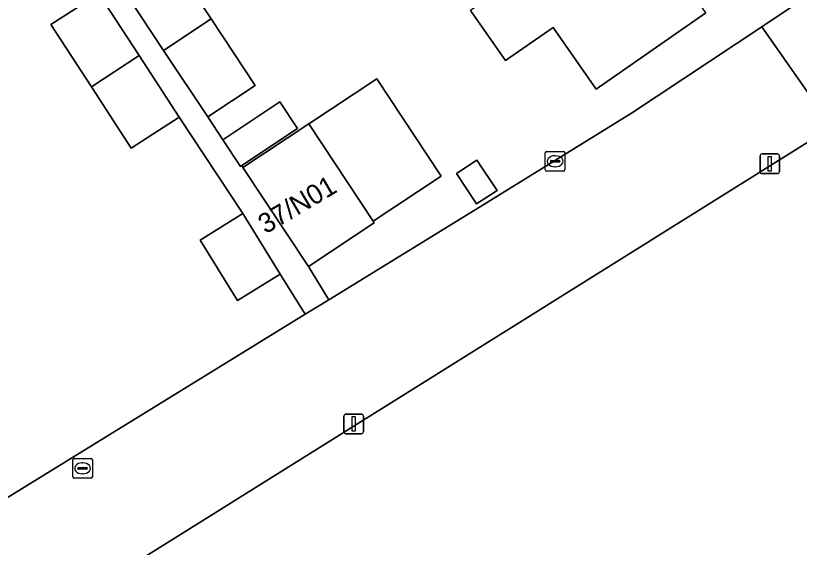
# Model space of a CAD drawing. Extents: x 159352 to 160617, y 385888 to 387323.
# Drawn here: x 159852.67 to 159892.59, y 386193.52 to 386220.6 of the extents above; entities that cross this region are included whole.
import ezdxf

# ---------------------------------------------------------------- set-up
doc = ezdxf.new("R2010")
doc.units = 0
for name, color, linetype in [('IMGEO_Erf', 7, 'Continuous'), ('IMGEO_Kolk', 7, 'Continuous'), ('IMGEO_Lichtmast', 7, 'Continuous'), ('IMGEO_Muur', 7, 'Continuous'), ('IMGEO_Pand', 7, 'Continuous'), ('IMGEO_Pand_nummerreeks', 7, 'Continuous'), ('IMGEO_Rijbaan_lokaal_open', 7, 'Continuous'), ('IMGEO_Voetpad_open', 7, 'Continuous')]:
    doc.layers.add(name, color=color, linetype=linetype)

msp = doc.modelspace()

# ---------------------------------------------------------------- linework, layer by layer
at = {"layer": 'IMGEO_Erf'}
for points in [[(159807.126, 386245.89), (159842.817, 386190.245), (159867.411, 386205.386), (159866.139, 386207.439), (159863.971, 386206.096), (159862.068, 386209.169), (159864.234, 386210.517), (159860.999, 386215.43), (159858.551, 386213.846), (159856.53, 386216.969), (159854.468, 386220.155), (159856.914, 386221.738), (159855.157, 386224.453), (159855.01, 386224.357), (159852.709, 386222.865), (159848.806, 386228.881), (159848.654, 386228.783), (159844.958, 386234.482)], [(159860.733, 386223.291), (159862.622, 386220.437), (159864.871, 386217.041), (159862.451, 386215.439), (159863.218, 386214.28), (159866.131, 386216.208), (159867.031, 386214.85), (159864.185, 386212.965), (159864.248, 386212.87), (159867.604, 386215.088), (159871.07, 386217.378), (159874.34, 386212.429), (159870.874, 386210.139), (159870.938, 386210.043), (159867.581, 386207.825), (159868.623, 386206.132), (159876.292, 386210.853), (159884.045, 386215.626), (159890.682, 386220.04), (159892.54, 386221.275)], [(159887.827, 386220.739), (159882.244, 386216.85), (159880.05, 386220.005), (159877.625, 386218.318), (159875.849, 386220.871)]]:
    msp.add_lwpolyline(points, dxfattribs=at)
msp.add_lwpolyline([(159875.128, 386212.559), (159876.17, 386213.247), (159877.191, 386211.702), (159876.149, 386211.013)], close=True, dxfattribs=at)
at = {"layer": 'IMGEO_Kolk'}
for p, q in [((159879.652, 386212.756), (159879.652, 386213.608)), ((159879.727, 386213.682), (159880.579, 386213.682)), ((159880.14, 386213.462), (159880.165, 386213.462)), ((159880.653, 386213.608), (159880.653, 386212.756)), ((159879.911, 386213.176), (159879.911, 386213.188)), ((159880.349, 386213.139), (159879.951, 386213.139)), ((159879.954, 386213.225), (159880.352, 386213.225)), ((159880.395, 386213.188), (159880.395, 386213.176)), ((159880.579, 386212.682), (159879.727, 386212.682)), ((159880.163, 386212.902), (159880.138, 386212.902)), ((159855.575, 386197.113), (159855.575, 386197.965)), ((159855.65, 386198.039), (159856.502, 386198.039)), ((159856.576, 386197.965), (159856.576, 386197.113)), ((159855.834, 386197.533), (159855.834, 386197.545)), ((159856.272, 386197.496), (159855.874, 386197.496)), ((159855.877, 386197.582), (159856.275, 386197.582)), ((159856.063, 386197.819), (159856.088, 386197.819)), ((159856.318, 386197.545), (159856.318, 386197.533)), ((159856.086, 386197.259), (159856.061, 386197.259)), ((159856.502, 386197.039), (159855.65, 386197.039))]:
    msp.add_line(p, q, dxfattribs=at)
for points in [[(159879.652, 386212.756), (159879.652, 386213.608)], [(159879.727, 386213.682), (159880.579, 386213.682)], [(159880.653, 386213.608), (159880.653, 386212.756)], [(159880.579, 386212.682), (159879.727, 386212.682)], [(159855.575, 386197.113), (159855.575, 386197.965)], [(159855.65, 386198.039), (159856.502, 386198.039)], [(159856.576, 386197.965), (159856.576, 386197.113)], [(159856.502, 386197.039), (159855.65, 386197.039)]]:
    msp.add_lwpolyline(points, dxfattribs=at)
for centre, radius, start, end in [((159879.729, 386213.606), 0.0765, 91.552, 178.448), ((159879.729, 386213.606), 0.0765, 91.552, 178.448), ((159880.577, 386213.606), 0.0765, 1.552, 88.448), ((159880.577, 386213.606), 0.0765, 1.552, 88.448), ((159879.951, 386213.185), 0.0403, 85.8775, 175.7526), ((159879.948, 386213.175), 0.0366, 178.938, 274.7102), ((159880.352, 386213.182), 0.043, 264.8664, 352.4533), ((159880.356, 386213.187), 0.0386, 1.7309, 96.639), ((159879.729, 386212.758), 0.0765, 181.552, 268.448), ((159879.729, 386212.758), 0.0765, 181.552, 268.448), ((159880.577, 386212.758), 0.0765, 271.552, 358.448), ((159880.577, 386212.758), 0.0765, 271.552, 358.448), ((159855.652, 386197.963), 0.0765, 91.552, 178.448), ((159855.652, 386197.963), 0.0765, 91.552, 178.448), ((159856.5, 386197.963), 0.0765, 1.552, 88.448), ((159856.5, 386197.963), 0.0765, 1.552, 88.448), ((159855.874, 386197.542), 0.0403, 85.8775, 175.7526), ((159855.871, 386197.532), 0.0366, 178.938, 274.7102), ((159856.275, 386197.539), 0.043, 264.8664, 352.4533), ((159856.279, 386197.544), 0.0386, 1.7309, 96.639), ((159855.652, 386197.115), 0.0765, 181.552, 268.448), ((159855.652, 386197.115), 0.0765, 181.552, 268.448), ((159856.5, 386197.115), 0.0765, 271.552, 358.448), ((159856.5, 386197.115), 0.0765, 271.552, 358.448)]:
    msp.add_arc(centre, radius, start, end, dxfattribs=at)
for centre, major_axis, ratio, start_param, end_param in [((159880.139, 386213.182), (-0.387, 0.002), 0.722429, 4.712389, 7.853982), ((159880.164, 386213.182), (-0.39, 0.002), 0.717154, 1.570796, 4.712389), ((159856.062, 386197.539), (-0.387, 0.002), 0.722429, 4.712389, 7.853982), ((159856.087, 386197.539), (-0.39, 0.002), 0.717154, 1.570796, 4.712389)]:
    msp.add_ellipse(centre, major_axis=major_axis, ratio=ratio, start_param=start_param, end_param=end_param, dxfattribs=at)
at = {"layer": 'IMGEO_Lichtmast'}
for p, q in [((159890.592, 386212.656), (159890.592, 386213.456)), ((159890.592, 386213.456), (159890.592, 386212.656)), ((159890.692, 386213.556), (159891.482, 386213.556)), ((159891.482, 386213.556), (159890.692, 386213.556)), ((159891.582, 386213.456), (159891.582, 386212.656)), ((159891.582, 386212.656), (159891.582, 386213.456)), ((159891.482, 386212.556), (159890.692, 386212.556)), ((159890.692, 386212.556), (159891.482, 386212.556)), ((159869.494, 386200.303), (159870.284, 386200.303)), ((159870.284, 386200.303), (159869.494, 386200.303)), ((159869.394, 386199.403), (159869.394, 386200.203)), ((159869.394, 386200.203), (159869.394, 386199.403)), ((159870.384, 386200.203), (159870.384, 386199.403)), ((159870.384, 386199.403), (159870.384, 386200.203)), ((159870.284, 386199.303), (159869.494, 386199.303)), ((159869.494, 386199.303), (159870.284, 386199.303))]:
    msp.add_line(p, q, dxfattribs=at)
for points in [[(159891.012, 386213.431), (159891.162, 386213.431), (159891.162, 386212.681), (159891.012, 386212.681), (159891.012, 386213.431)], [(159869.814, 386200.178), (159869.964, 386200.178), (159869.964, 386199.428), (159869.814, 386199.428), (159869.814, 386200.178)]]:
    msp.add_lwpolyline(points, dxfattribs=at)
for centre, start, end in [((159890.692, 386213.456), 90, 180), ((159890.692, 386213.456), 90, 180), ((159891.482, 386213.456), 0, 90), ((159891.482, 386213.456), 360, 90), ((159890.692, 386212.656), 180, 270), ((159890.692, 386212.656), 180, 270), ((159891.482, 386212.656), 270, 0), ((159891.482, 386212.656), 270, 0), ((159869.494, 386200.203), 90, 180), ((159869.494, 386200.203), 90, 180), ((159870.284, 386200.203), 0, 90), ((159870.284, 386200.203), 360, 90), ((159869.494, 386199.403), 180, 270), ((159869.494, 386199.403), 180, 270), ((159870.284, 386199.403), 270, 0), ((159870.284, 386199.403), 270, 0)]:
    msp.add_arc(centre, 0.1, start, end, dxfattribs=at)
at = {"layer": 'IMGEO_Muur'}
msp.add_lwpolyline([(159876.292, 386210.853), (159884.045, 386215.626)], dxfattribs=at)
at = {"layer": 'IMGEO_Pand'}
for points in [[(159883.85, 386226.448), (159878.275, 386222.556), (159875.849, 386220.871), (159877.625, 386218.318), (159880.05, 386220.005), (159882.244, 386216.85), (159887.827, 386220.739)], [(159858.313, 386221.689), (159860.203, 386218.835), (159862.622, 386220.437), (159860.733, 386223.291)], [(159856.914, 386221.738), (159854.468, 386220.155), (159856.53, 386216.969), (159858.966, 386218.567)], [(159862.622, 386220.437), (159860.203, 386218.835), (159862.451, 386215.439), (159864.871, 386217.041)], [(159858.966, 386218.567), (159856.53, 386216.969), (159858.551, 386213.846), (159860.999, 386215.43)], [(159867.604, 386215.088), (159870.874, 386210.139), (159874.34, 386212.429), (159871.07, 386217.378)], [(159863.218, 386214.28), (159864.118, 386212.921), (159864.185, 386212.965), (159867.031, 386214.85), (159866.131, 386216.208)], [(159894.419, 386214.707), (159893.304, 386214.01), (159893.163, 386214.236), (159850.354, 386187.472), (159855.41, 386179.385), (159856.468, 386180.046), (159861.631, 386171.83), (159862.318, 386172.259), (159903.24, 386197.844), (159897.175, 386207.545), (159898.938, 386208.648), (159894.944, 386215.035)], [(159867.604, 386215.088), (159864.248, 386212.87), (159867.581, 386207.825), (159870.938, 386210.043), (159870.874, 386210.139)], [(159875.128, 386212.559), (159876.149, 386211.013), (159877.191, 386211.702), (159876.17, 386213.247)], [(159866.139, 386207.439), (159864.234, 386210.517), (159862.068, 386209.169), (159863.971, 386206.096)]]:
    msp.add_lwpolyline(points, close=True, dxfattribs=at)
at = {"layer": 'IMGEO_Rijbaan_lokaal_open'}
msp.add_lwpolyline([(159893.163, 386214.236), (159893.304, 386214.01), (159894.419, 386214.707), (159890.682, 386220.04), (159884.045, 386215.626), (159876.292, 386210.853), (159868.623, 386206.132), (159867.411, 386205.386), (159842.817, 386190.245), (159846.244, 386184.902), (159850.354, 386187.472)], close=True, dxfattribs=at)
at = {"layer": 'IMGEO_Voetpad_open'}
for points in [[(159851.33, 386280.261), (159853.707, 386276.934), (159892.54, 386221.275), (159890.682, 386220.04), (159894.419, 386214.707), (159894.944, 386215.035), (159898.938, 386208.648), (159897.175, 386207.545), (159903.24, 386197.844), (159911.754, 386203.296), (159911.602, 386203.516)], [(159851.112, 386230.367), (159853.432, 386226.79), (159855.01, 386224.357), (159855.157, 386224.453), (159856.914, 386221.738), (159858.966, 386218.567), (159860.999, 386215.43), (159864.234, 386210.517), (159866.139, 386207.439), (159867.411, 386205.386), (159868.623, 386206.132), (159867.581, 386207.825), (159864.248, 386212.87), (159864.185, 386212.965), (159864.118, 386212.921), (159863.218, 386214.28), (159862.451, 386215.439), (159860.203, 386218.835), (159858.313, 386221.689), (159856.597, 386224.379), (159852.961, 386229.948), (159849.093, 386235.871)]]:
    msp.add_lwpolyline(points, dxfattribs=at)

# ---------------------------------------------------------------- texts
at = {"layer": 'IMGEO_Pand_nummerreeks'}
msp.add_text('37/N01', height=1, rotation=30.5387, dxfattribs=at).set_placement((159865.402, 386209.458))

doc.saveas('drawing.dxf')
